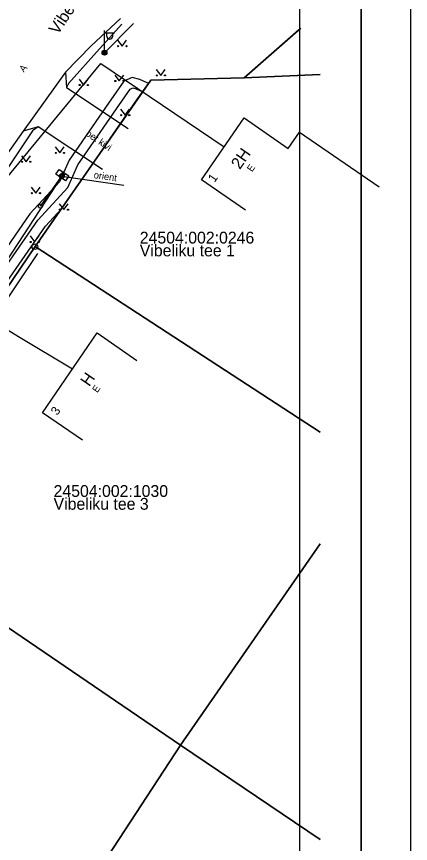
# Model space of a CAD drawing. Extents: x 553261 to 553443, y 6588794 to 6589074.
# Drawn here: x 553403.3 to 553443.3, y 6588946 to 6589029.9 of the extents above; entities that cross this region are included whole.
import ezdxf

# ---------------------------------------------------------------- set-up
doc = ezdxf.new("R2010")
doc.units = 0
for name, color, linetype in [('ELRAJATISMP', 7, 'Continuous'), ('HALJASTUS', 7, 'Continuous'), ('HOONE', 7, 'Continuous'), ('KASUTUSALA', 7, 'Continuous'), ('MPKAABEL', 7, 'Continuous'), ('MPOHULIIN', 7, 'Continuous'), ('PIIR', 7, 'Continuous'), ('PIIRIMLEITUD', 7, 'Continuous'), ('POST', 7, 'Continuous'), ('PR_SIDE', 7, 'Continuous'), ('SITRASS', 7, 'Continuous'), ('TEE', 7, 'Continuous'), ('VORMISTUS_1', 7, 'Continuous')]:
    doc.layers.add(name, color=color, linetype=linetype)

msp = doc.modelspace()

# ---------------------------------------------------------------- linework, layer by layer
at = {"layer": 'ELRAJATISMP'}
for p, q in [((553408.036, 6589014.118), (553407.703, 6589013.623)), ((553408.261, 6589013.967), (553407.928, 6589013.471))]:
    msp.add_line(p, q, dxfattribs=at)
msp.add_lwpolyline([(553407.652, 6589014.376), (553408.644, 6589013.709), (553408.311, 6589013.214), (553407.32, 6589013.88)], close=True, dxfattribs=at)
at = {"layer": 'HALJASTUS'}
for p, q in [((553413.586, 6589027.48), (553414.049, 6589026.873)), ((553414.049, 6589026.873), (553414.495, 6589027.48)), ((553413.294, 6589023.946), (553413.758, 6589023.339)), ((553413.758, 6589023.339), (553414.203, 6589023.946)), ((553417.494, 6589024.512), (553417.958, 6589023.906)), ((553417.958, 6589023.906), (553418.403, 6589024.512)), ((553409.677, 6589023.535), (553410.141, 6589022.928)), ((553410.141, 6589022.928), (553410.586, 6589023.535)), ((553413.877, 6589020.481), (553414.34, 6589019.875)), ((553414.34, 6589019.875), (553414.786, 6589020.481)), ((553407.257, 6589016.651), (553407.721, 6589016.044)), ((553407.721, 6589016.044), (553408.166, 6589016.651)), ((553403.847, 6589015.752), (553404.311, 6589015.145)), ((553404.311, 6589015.145), (553404.756, 6589015.752)), ((553404.825, 6589012.564), (553405.288, 6589011.958)), ((553405.288, 6589011.958), (553405.733, 6589012.564)), ((553407.671, 6589010.894), (553408.135, 6589010.288)), ((553408.135, 6589010.288), (553408.58, 6589010.894)), ((553404.711, 6589007.619), (553405.174, 6589007.012)), ((553405.174, 6589007.012), (553405.62, 6589007.619)), ((553405.456, 6589005.84), (553398.044, 6588994.79))]:
    msp.add_line(p, q, dxfattribs=at)
for centre in [(553413.648, 6589026.873), (553414.477, 6589026.873), (553417.556, 6589023.906), (553418.385, 6589023.906), (553413.357, 6589023.339), (553414.185, 6589023.339), (553409.739, 6589022.928), (553410.568, 6589022.928), (553413.939, 6589019.875), (553414.768, 6589019.875), (553407.32, 6589016.044), (553408.149, 6589016.044), (553403.91, 6589015.145), (553404.739, 6589015.145), (553404.887, 6589011.958), (553405.716, 6589011.958), (553407.734, 6589010.288), (553408.562, 6589010.288), (553404.773, 6589007.012), (553405.602, 6589007.012)]:
    msp.add_circle(centre, 0.055, dxfattribs=at)
at = {"layer": 'HOONE'}
for points in [[(553426.55, 6589010.22), (553422.07, 6589013.31), (553426.4, 6589019.59), (553430.88, 6589016.5), (553432.02, 6589018.16), (553440.08, 6589012.61)], [(553410.03, 6588986.9), (553405.99, 6588989.69), (553411.5, 6588997.78), (553415.54, 6588994.99)]]:
    msp.add_lwpolyline(points, dxfattribs=at)
at = {"layer": 'KASUTUSALA'}
msp.add_lwpolyline([(553400.919, 6589000.902), (553406.271, 6589008.606), (553407.899, 6589010.376), (553410.045, 6589013.472), (553415.548, 6589021.411), (553416.699, 6589023.073), (553416.567, 6589023.139), (553415.823, 6589023.506), (553415.058, 6589023.69), (553414.212, 6589023.335), (553412.647, 6589021.084), (553408.679, 6589015.315), (553407.686, 6589013.1), (553404.707, 6589009.859), (553399.243, 6589001.994)], dxfattribs=at)
at = {"layer": 'MPKAABEL'}
for p, q in [((553412.257, 6589026.208), (553415.189, 6589029.182)), ((553407.936, 6589013.677), (553414.227, 6589012.779))]:
    msp.add_line(p, q, dxfattribs=at)
at = {"layer": 'MPOHULIIN'}
msp.add_lwpolyline([(553407.936, 6589013.677), (553396.681, 6588996.514), (553396.681, 6588996.514), (553386.407, 6588980.817), (553375.68, 6588963.935), (553363.057, 6588946.078)], dxfattribs=at)
at = {"layer": 'PIIR'}
for points in [[(553431.953, 6589028.538), (553426.41, 6589023.65), (553416.94, 6589023.42), (553405.24, 6589006.54), (553386.47, 6588978.82), (553366.97, 6588950.29), (553347.5, 6588922.26), (553328.32, 6588893.48), (553310.97, 6588866.48), (553295.9, 6588840.93), (553293.3, 6588836.47), (553287.77, 6588819.195)], [(553434.11, 6589024.001), (553426.41, 6589023.65), (553432.148, 6589028.711)], [(553434.11, 6588987.72), (553405.24, 6589006.54), (553416.94, 6589023.42), (553426.41, 6589023.65), (553434.11, 6589024.001)], [(553434.11, 6588976.398), (553419.97, 6588955.97), (553386.47, 6588978.82), (553405.24, 6589006.54), (553434.11, 6588987.72)], [(553434.11, 6588946.413), (553419.97, 6588955.97), (553434.11, 6588976.398)], [(553434.11, 6588908.824), (553432.54, 6588906.54), (553401.3, 6588927.47), (553419.97, 6588955.97), (553434.11, 6588946.413)]]:
    msp.add_lwpolyline(points, dxfattribs=at)
msp.add_lwpolyline([(553366.97, 6588950.29), (553386.47, 6588978.82), (553419.97, 6588955.97), (553401.3, 6588927.47)], close=True, dxfattribs=at)
at = {"layer": 'PIIRIMLEITUD'}
msp.add_circle((553405.203, 6589006.532), 0.285, dxfattribs=at)
at = {"layer": 'POST'}
for p, q in [((553412.257, 6589026.458), (553412.257, 6589028.458)), ((553412.257, 6589028.208), (553413.257, 6589028.208)), ((553412.484, 6589027.887), (553412.484, 6589028.208)), ((553413.097, 6589027.887), (553413.097, 6589028.208)), ((553412.257, 6589026.208), (553412.257, 6589026.208))]:
    msp.add_line(p, q, dxfattribs=at)
msp.add_lwpolyline([(553405.764, 6589010.634), (553407.936, 6589013.677)], dxfattribs=at)
for centre, radius in [((553412.257, 6589026.208), 0.25), ((553412.257, 6589026.208), 0.225), ((553412.257, 6589026.208), 0.2), ((553412.257, 6589026.208), 0.175), ((553412.257, 6589026.208), 0.15), ((553412.257, 6589026.208), 0.125), ((553412.257, 6589026.208), 0.1), ((553412.257, 6589026.208), 0.075), ((553412.257, 6589026.208), 0.05), ((553412.257, 6589026.208), 0.025), ((553407.936, 6589013.677), 0.25), ((553405.764, 6589010.634), 0.2)]:
    msp.add_circle(centre, radius, dxfattribs=at)
msp.add_arc((553412.79, 6589027.887), 0.306, 180, 0, dxfattribs=at)
at = {"layer": 'PR_SIDE'}
msp.add_lwpolyline([(553399.139, 6588999.905), (553400.081, 6589001.448), (553405.489, 6589009.233), (553408.532, 6589012.542), (553409.554, 6589014.823), (553413.47, 6589020.515), (553414.867, 6589022.525), (553415.143, 6589022.641), (553415.48, 6589022.56), (553416.124, 6589022.242)], dxfattribs=at)
at = {"layer": 'SITRASS'}
for points in [[(553371.515, 6588943.799), (553371.28, 6588945.87), (553369.98, 6588947.79), (553361.86, 6588954.66), (553374.16, 6588971.25), (553381.59, 6588982.6), (553395.2, 6589002.56), (553401.87, 6589012.9), (553411.9, 6589025.12), (553419.37, 6589020.03), (553424.388, 6589016.672)], [(553395.2, 6589002.56), (553403.55, 6588997.42), (553409.017, 6588994.134)]]:
    msp.add_lwpolyline(points, dxfattribs=at)
at = {"layer": 'TEE'}
for points in [[(553413.877, 6589029.661), (553410.908, 6589026.905), (553408.292, 6589024.218), (553404.003, 6589018.245), (553398.361, 6589010.315)], [(553414.019, 6589029.1), (553411.748, 6589026.599), (553408.593, 6589023.096), (553408.414, 6589022.695)], [(553408.292, 6589024.218), (553408.414, 6589022.695), (553414.652, 6589018.52)], [(553405.552, 6589018.694), (553404.957, 6589018.27), (553399.27, 6589009.775), (553392.603, 6589000.577), (553391.649, 6588998.522)], [(553412.07, 6589014.347), (553405.552, 6589018.694), (553404.003, 6589018.245)]]:
    msp.add_lwpolyline(points, dxfattribs=at)
at = {"layer": 'VORMISTUS_1'}
for points in [[(553338.255, 6589062.04), (553443.255, 6589062.04), (553443.255, 6588913.54), (553338.255, 6588913.54)], [(553343.255, 6588919.04), (553438.255, 6588919.04), (553438.255, 6589056.54), (553343.255, 6589056.54)], [(553343.255, 6589056.54), (553438.255, 6589056.54), (553438.255, 6588919.04), (553343.255, 6588919.04)], [(553432.005, 6588932.04), (553349.505, 6588932.04), (553349.505, 6589037.04), (553432.005, 6589037.04)]]:
    msp.add_lwpolyline(points, close=True, dxfattribs=at)

# ---------------------------------------------------------------- texts
at = {"layer": 'HOONE'}
for s, height, rotation, p in [('2H', 1.2, 55.41411, (553425.972, 6589014.3)), ('E', 0.7, 55.41411, (553427.205, 6589014.063)), ('1', 0.9, 55.36848, (553423.41, 6589012.991)), ('H', 1.2, 55.41411, (553410.706, 6588992.273)), ('E', 0.7, 55.41411, (553411.525, 6588991.663)), ('3', 0.9, 55.69608, (553407.476, 6588989.363))]:
    msp.add_text(s, height=height, rotation=rotation, dxfattribs=at).set_placement(p)
at = {"layer": 'MPKAABEL'}
msp.add_text('orient', height=0.7, rotation=351.83078, dxfattribs=at).set_placement((553411.135, 6589013.489))
at = {"layer": 'PIIR'}
for s, p in [('24504:002:0246', (553415.831, 6589006.851)), ('Vibeliku tee 1', (553415.831, 6589005.551)), ('24504:002:1030', (553407.097, 6588981.149)), ('Vibeliku tee 3', (553407.097, 6588979.849))]:
    msp.add_text(s, height=1.2, dxfattribs=at).set_placement(p)
at = {"layer": 'TEE'}
for s, height, rotation, p in [('Vibeliku tee', 1.2, 56.06109, (553407.521, 6589027.962)), ('A', 0.7, 51.6331, (553404.091, 6589024.169)), ('bet kivi', 0.7, 325.59454, (553410.283, 6589017.859))]:
    msp.add_text(s, height=height, rotation=rotation, dxfattribs=at).set_placement(p)

doc.saveas('drawing.dxf')
